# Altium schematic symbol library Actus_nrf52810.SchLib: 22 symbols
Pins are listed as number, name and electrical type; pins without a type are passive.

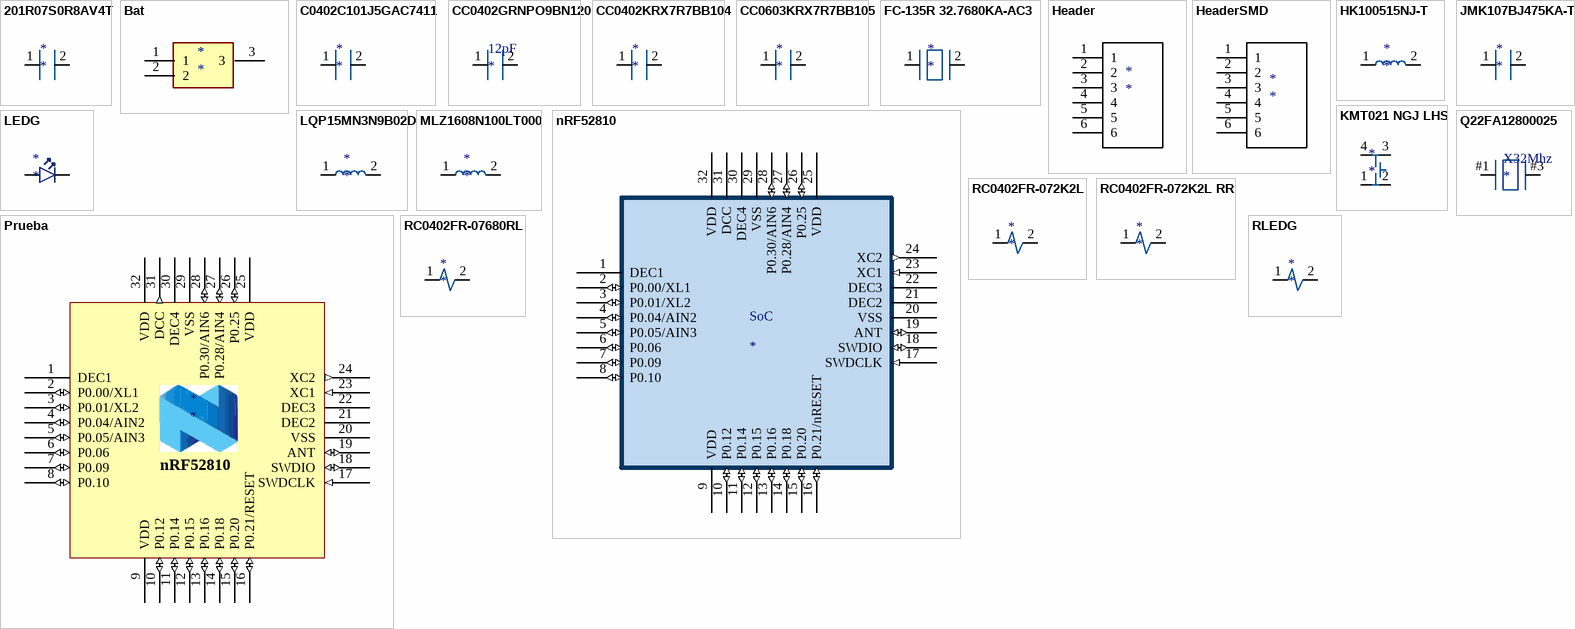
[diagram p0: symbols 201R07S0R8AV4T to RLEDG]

## 201R07S0R8AV4T
designator *
C3: 0.8pF, 0402, Johanson Dielectrics
footprint 201R07S0R8AV4T (C3, 0.8pF, 0402, Johanson Dielectrics (Dimensiones no especificadas en datasheet, medidas tomadas de Mouser))
pins: 1, 2

## Bat
designator *
footprint Bat
pins: 1, 2, 3

## C0402C101J5GAC7411
designator *
C7: 100 pF, 0402, KEMET
footprint C0402C101J5GAC7411 (C7: 100 pF, 0402, KEMET)
pins: 1, 2

## CC0402GRNPO9BN120
designator 12pF
C1, C2, C11, C12:  12pF, 0402, Yageo
footprint CC0402GRNPO9BN120 (C1, C2, C11, C12: 12pF, 0402, Yageo)
footprint CC0402GRNPO9BN120 (C1, C2, C11, C12: 12pF, 0402, Yageo)
pins: 1, 2

## CC0402KRX7R7BB104
designator *
C4, C5, C8 : 100nF (0.1uF), 0402, Yageo
footprint CC0402KRX7R7BB104 (C4, C5, C8: 100nF (0.1uF), 0402, Yageo)
pins: 1, 2

## CC0603KRX7R7BB105
designator *
C10: 1.0uF, 0603, Yageo
footprint CC0603KRX7R7BB105 (C10: 1.0uF, 0603, Yageo)
pins: 1, 2

## FC-135R 32.7680KA-AC3
designator *
X2: 32.7680KHZ, XTAL_3215, EPSON
footprint FC-135R 32.7680KA-AC3 (X2: 32.7680KHZ, XTAL_3215, EPSON)
pins: 1, 2

## Header
designator *
pins: 1, 2, 3, 4, 5, 6

## HeaderSMD
designator *
footprint Header SMD
pins: 1, 2, 3, 4, 5, 6

## HK100515NJ-T
designator *
L3: 15nH, 0402, Taiyo Yuden
footprint HK100515NJ-T (L3: 15nH, 0402, Taiyo Yuden)
pins: 1, 2

## JMK107BJ475KA-T
designator *
C9: 4.7uF, 0603, Taiyo Yuden
footprint JMK107BJ475KA-T
pins: 1, 2

## KMT021 NGJ LHS
designator *
Micro-Switch
footprint Switch
pins: 1 2, 2, 3, 4 1

## LEDG
designator *
footprint LEDG
pins: 1 C, 2 A

## LQP15MN3N9B02D
designator *
L1: 3.9 nH, 0402 (1005 metric), Murata Electronics
footprint LQP15MN3N9B02D (L1: 3.9 nH, 0402 (1005 metric), Murata Electronics)
pins: 1, 2

## MLZ1608N100LT000
designator *
L2: 10 uH, 0603 (1608 metric), TDK
footprint MLZ1608N100LT000 (L2: 10 uH, 0603 (1608 metric), TDK)
pins: 1, 2

## nRF52810
designator SoC
QCAA - QFN-32
footprint nRF52810 (QFN, 32-Leads, Body 5.00x5.00mm, Pitch 0.50mm, Thermal Pad 3.50x3.50mm, IPC Medium Density)
pins: 1 DEC1 (power) "0.9 V regulator digital supply decoupling", 2 P0.00/XL1 (io) "General purpose I/O /Connection for 32.768 kHz crystal (LFXO)", 3 P0.01/XL2 (io) "General purpose / I/O Connection for 32.768 kHz crystal (LFXO)", 4 P0.04/AIN2 (io) "General purpose / I/O COMP input / SAADC input", 5 P0.05/AIN3 (io) "General purpose I/O / COMP input / SAADC input", 6 P0.06 (io) "General purpose I/O", 7 P0.09 (io) "General purpose I/O", 8 P0.10 (io) "General purpose I/O", 9 VDD (power) "Power Supply", 10 P0.12 (io) "General purpose I/O", 11 P0.14 (io) "General purpose I/O", 12 P0.15 (io) "General purpose I/O", 13 P0.16 (io) "General purpose I/O", 14 P0.18 (io) "General purpose I/O / Single wire output", 15 P0.20 (io) "General purpose I/O", 16 P0.21/nRESET (io) "General purpose I/O / Configurable as pin Reset", 17 SWDCLK (in) "Serial wire debug clock input for debug and programming", 18 SWDIO (io) "Serial wire debug I/O for debug and programming", 19 ANT (io) "Single-ended radio antenna connection", 20 VSS (power) "Ground (radio supply)", 21 DEC2 (power) "1.3 V regulator supply decoupling (radio supply)", 22 DEC3 (power) "Power supply decoupling", 23 XC1 (in) "Connection for 32 MHz crystal", 24 XC2 (out) "Connection for 32 MHz crystal", 25 VDD (power) "Power supply", 26 P0.25 (io) "General purpose I/O", 27 P0.28/AIN4 (io) "General purpose I/O / COMP input / SAADC input", 28 P0.30/AIN6 (io) "General purpose I/O / COMP input / SAADC input", 29 VSS (power) "Ground", 30 DEC4 (power) "1.3 V regulator supply decoupling / Input from DC/DC regulator / Output from 1.3 V LDO", 31 DCC (power) "DC/DC regulator output", 32 VDD (power) "Power supply"

## Prueba
designator *
footprint Prueba2
pins: 1 DEC1 (power), 2 P0.00/XL1 (io), 3 P0.01/XL2 (io), 4 P0.04/AIN2 (io), 5 P0.05/AIN3 (io), 6 P0.06 (io), 7 P0.09 (io), 8 P0.10 (io), 9 VDD (power), 10 P0.12 (io), 11 P0.14 (io), 12 P0.15 (io), 13 P0.16 (io), 14 P0.18 (io), 15 P0.20 (io), 16 P0.21/RESET (io), 17 SWDCLK (in), 18 SWDIO (io), 19 ANT (io), 20 VSS (power), 21 DEC2 (power), 22 DEC3 (power), 23 XC1 (in), 24 XC2 (out), 25 VDD (power), 26 P0.25 (io), 27 P0.28/AIN4 (io), 28 P0.30/AIN6 (io), 29 VSS (power), 30 DEC4 (power), 31 DCC (out), 32 VDD (power)

## Q22FA12800025
designator X32Mhz
X1: 32MHz, XTAL_2016, EPSON
footprint Q22FA12800025
pins: #1, #3

## RC0402FR-072K2L
designator *
RB: 820 Ohms, 0402, Yageo
footprint RC0402FR-07820RL (RB: 820 Ohms, 0402, Yageo)
pins: 1, 2

## RC0402FR-072K2L RR
designator *
RR: 2.2kOhms, 0402, Yageo
footprint RC0402FR-072K2L RR (RR: 2.2kOhms, 0402, Yageo)
pins: 1, 2

## RC0402FR-07680RL
designator *
RG: 680 Ohms, 0402, Yageo
footprint RC0402FR-07680RL (RG: 680 Ohms, 0402, Yageo)
pins: 1, 2

## RLEDG
designator *
footprint RLEDG
pins: 1, 2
